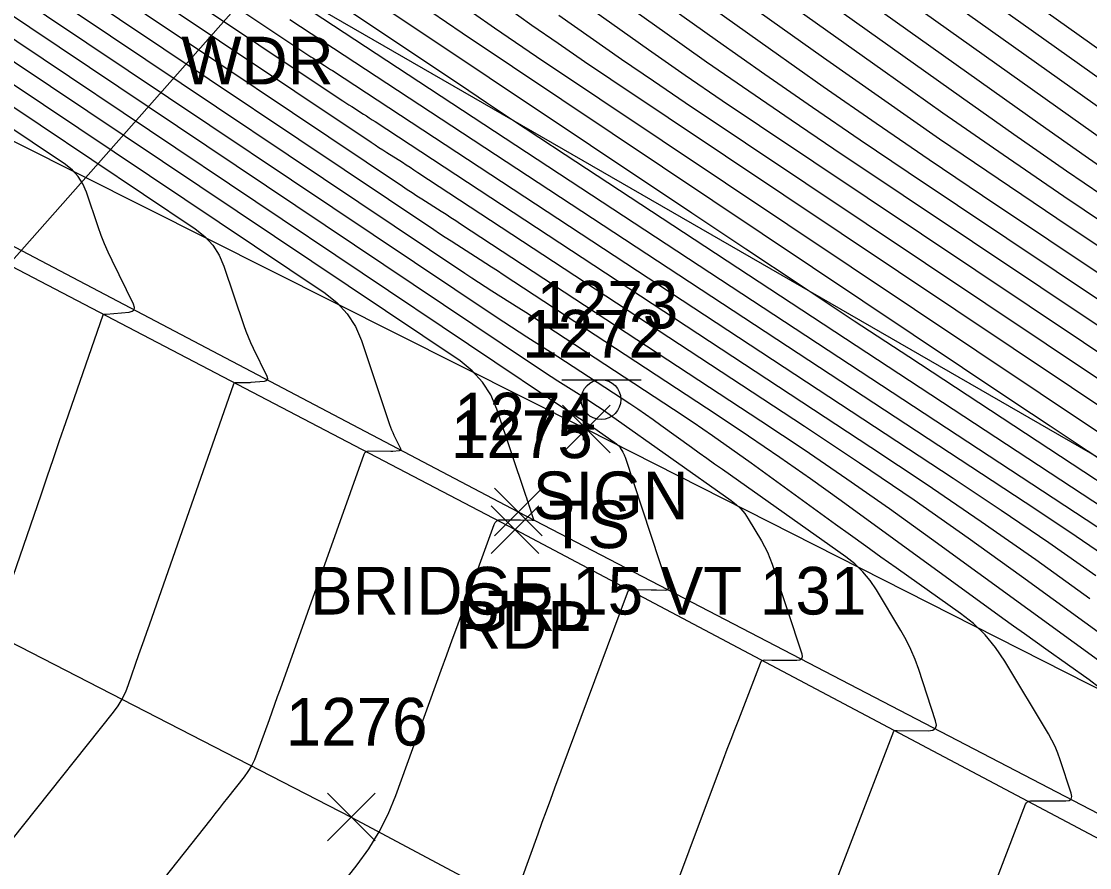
# Model space of a CAD drawing. Extents: x 1650836 to 1652450, y 332578 to 333908.
# Drawn here: x 1652137.1 to 1652181.92, y 332766.98 to 332802.49 of the extents above; entities that cross this region are included whole.
import ezdxf

# ---------------------------------------------------------------- set-up
doc = ezdxf.new("R2010")
doc.units = 0
for name, color, linetype in [('DCP', 7, 'Continuous'), ('L_A', 7, 'Continuous'), ('L_I', 7, 'Continuous'), ('L_TIC', 7, 'Continuous'), ('LAWA', 7, 'Continuous'), ('LELB', 7, 'Continuous'), ('LSOGCMA', 7, 'Continuous'), ('LSOGCMI', 7, 'Continuous'), ('P_A', 7, 'Continuous'), ('P_I', 7, 'Continuous'), ('P_TIC', 7, 'Continuous'), ('PET', 7, 'Continuous'), ('PRC', 7, 'Continuous'), ('R_A', 7, 'Continuous'), ('R_I', 7, 'Continuous'), ('R_TIC', 7, 'Continuous'), ('RGR', 7, 'Continuous'), ('S_A', 7, 'Continuous'), ('S_C', 7, 'Continuous'), ('S_I', 7, 'Continuous'), ('SSGN', 7, 'Continuous')]:
    doc.layers.add(name, color=color, linetype=linetype)

msp = doc.modelspace()

# ---------------------------------------------------------------- linework, layer by layer
at = {"layer": 'DCP'}
msp.add_lwpolyline([(1652097.436, 332748.039), (1652173.064, 332833.561)], dxfattribs=at)
at = {"layer": 'L_TIC'}
for points in [[(1652159.81, 332784.384), (1652161.81, 332786.384)], [(1652161.81, 332784.384), (1652159.81, 332786.384)]]:
    msp.add_lwpolyline(points, dxfattribs=at)
at = {"layer": 'LAWA'}
msp.add_lwpolyline([(1652408.76, 332665.713), (1652363.38, 332695.402), (1652324.46, 332714.991), (1652289.155, 332735.895), (1652253.497, 332747.946), (1652218.614, 332766.122), (1652198.198, 332775.017), (1652146.456, 332804.843), (1652136.841, 332807.592), (1652091.374, 332831.511), (1652057.601, 332848.138), (1652027.653, 332867.625)], dxfattribs=at)
at = {"layer": 'LELB'}
msp.add_lwpolyline([(1652023.441, 332859.649), (1652034.235, 332853.429), (1652052.246, 332842.357), (1652084.686, 332826.36), (1652123.711, 332804.04), (1652160.81, 332785.384), (1652195.281, 332767.897), (1652235.573, 332746.682), (1652255.289, 332735.81), (1652296.57, 332712.591), (1652348.8, 332686.345), (1652380.841, 332668.301), (1652404.073, 332656.539)], dxfattribs=at)
at = {"layer": 'LSOGCMA'}
for points in [[(1652192.271, 332793.06), (1652191.611, 332793.511), (1652190.679, 332794.159), (1652189.751, 332794.813), (1652162.63, 332814.09)], [(1652210.348, 332769.549), (1652210.332, 332769.56), (1652209.691, 332770.012), (1652209.05, 332770.464), (1652208.411, 332770.918), (1652202.726, 332774.956), (1652202.301, 332775.254), (1652201.873, 332775.548), (1652201.442, 332775.838), (1652201.008, 332776.124), (1652199.268, 332777.257), (1652198.833, 332777.541), (1652198.399, 332777.826), (1652197.966, 332778.113), (1652197.534, 332778.401), (1652168.073, 332798.103), (1652166.511, 332799.156), (1652164.957, 332800.22), (1652163.41, 332801.294), (1652161.871, 332802.38), (1652153.245, 332808.511)], [(1652129.2, 332803.974), (1652144.4, 332793.781), (1652144.8, 332793.465), (1652145.134, 332793.098), (1652145.4, 332792.68), (1652145.6, 332792.211), (1652146.436, 332789.728), (1652146.521, 332789.487), (1652146.615, 332789.249), (1652146.716, 332789.014), (1652146.824, 332788.783), (1652147.405, 332787.595), (1652147.433, 332787.509), (1652147.423, 332787.445), (1652147.374, 332787.403), (1652147.286, 332787.382), (1652146.735, 332787.329), (1652146.691, 332787.325), (1652146.646, 332787.323), (1652146.601, 332787.321), (1652146.556, 332787.321), (1652146.093, 332787.326), (1652146.064, 332787.322), (1652146.04, 332787.311), (1652146.021, 332787.292), (1652146.008, 332787.266), (1652142.46, 332777.156), (1652142.35, 332776.844), (1652142.241, 332776.531), (1652142.132, 332776.218), (1652142.023, 332775.905), (1652141.587, 332774.652), (1652141.466, 332774.346), (1652141.321, 332774.053), (1652141.151, 332773.773), (1652140.957, 332773.507), (1652137.194, 332768.775), (1652136.758, 332768.228)], [(1652143.66, 332803.799), (1652150.474, 332799.23), (1652150.595, 332799.149), (1652150.717, 332799.068), (1652150.84, 332798.989), (1652150.963, 332798.91), (1652151.456, 332798.597), (1652151.579, 332798.518), (1652151.702, 332798.439), (1652151.824, 332798.36), (1652151.947, 332798.28), (1652172.746, 332784.625), (1652175.072, 332783.078), (1652177.379, 332781.504), (1652179.667, 332779.903), (1652181.936, 332778.274)]]:
    msp.add_lwpolyline(points, dxfattribs=at)
at = {"layer": 'LSOGCMI'}
for points in [[(1652163.362, 332814.795), (1652192.807, 332793.866)], [(1652191.755, 332792.283), (1652191.471, 332792.472), (1652190.206, 332793.324), (1652188.948, 332794.186), (1652187.696, 332795.056), (1652186.45, 332795.935), (1652161.897, 332813.386)], [(1652161.078, 332812.743), (1652183.149, 332797.056), (1652184.713, 332795.952), (1652186.285, 332794.86), (1652187.865, 332793.779), (1652189.452, 332792.709), (1652191.243, 332791.512)], [(1652160.099, 332812.214), (1652179.848, 332798.177), (1652181.73, 332796.849), (1652183.622, 332795.535), (1652185.524, 332794.234), (1652187.434, 332792.946), (1652190.731, 332790.741)], [(1652211.579, 332775.823), (1652210.221, 332776.757), (1652208.854, 332777.677), (1652207.477, 332778.583), (1652201.697, 332782.345), (1652200.275, 332783.274), (1652198.856, 332784.207), (1652197.439, 332785.145), (1652196.026, 332786.087), (1652185.416, 332793.183), (1652183.182, 332794.688), (1652180.959, 332796.209), (1652178.748, 332797.746), (1652176.547, 332799.299), (1652159.12, 332811.685)], [(1652217.504, 332770.432), (1652211.296, 332774.841), (1652210.067, 332775.704), (1652208.829, 332776.555), (1652207.583, 332777.393), (1652206.329, 332778.219), (1652201.292, 332781.497), (1652200.035, 332782.318), (1652198.779, 332783.144), (1652197.527, 332783.973), (1652196.277, 332784.806), (1652183.397, 332793.42), (1652180.841, 332795.143), (1652178.297, 332796.884), (1652175.765, 332798.643), (1652173.246, 332800.42), (1652158.141, 332811.156)], [(1652217.634, 332769.145), (1652209.582, 332774.864), (1652208.514, 332775.614), (1652207.438, 332776.354), (1652206.355, 332777.082), (1652205.265, 332777.8), (1652200.887, 332780.649), (1652199.794, 332781.363), (1652198.703, 332782.08), (1652197.615, 332782.801), (1652196.528, 332783.525), (1652180.544, 332794.215), (1652178.081, 332795.875), (1652175.63, 332797.552), (1652173.19, 332799.247), (1652170.763, 332800.959), (1652157.161, 332810.627)], [(1652156.182, 332810.098), (1652168.54, 332801.315), (1652170.745, 332799.759), (1652172.961, 332798.219), (1652175.188, 332796.695), (1652177.426, 332795.187), (1652196.78, 332782.244), (1652197.703, 332781.629), (1652198.627, 332781.017), (1652199.554, 332780.407), (1652200.482, 332779.801), (1652204.2, 332777.381), (1652205.127, 332776.771), (1652206.047, 332776.152), (1652206.961, 332775.524), (1652207.868, 332774.887), (1652212.045, 332771.92)], [(1652155.203, 332809.569), (1652166.317, 332801.67), (1652168.3, 332800.271), (1652170.293, 332798.886), (1652172.296, 332797.515), (1652174.309, 332796.159), (1652197.031, 332780.963), (1652197.79, 332780.457), (1652198.551, 332779.953), (1652199.314, 332779.452), (1652200.078, 332778.953), (1652203.136, 332776.962), (1652203.899, 332776.46), (1652204.656, 332775.951), (1652205.407, 332775.434), (1652206.154, 332774.91), (1652211.479, 332771.128)], [(1652210.912, 332770.336), (1652204.44, 332774.933), (1652203.854, 332775.344), (1652203.264, 332775.75), (1652202.67, 332776.149), (1652202.072, 332776.543), (1652199.673, 332778.105), (1652199.073, 332778.496), (1652198.475, 332778.889), (1652197.878, 332779.285), (1652197.282, 332779.682), (1652171.191, 332797.131), (1652169.404, 332798.336), (1652167.625, 332799.553), (1652165.855, 332800.783), (1652164.094, 332802.025), (1652154.224, 332809.04)], [(1652146.574, 332804.702), (1652183.123, 332780.708), (1652184.5, 332779.792), (1652185.867, 332778.859), (1652187.222, 332777.911), (1652188.566, 332776.946), (1652195.288, 332772.06), (1652195.944, 332771.586), (1652196.601, 332771.114), (1652197.261, 332770.646), (1652197.922, 332770.18), (1652200.572, 332768.322), (1652201.234, 332767.856), (1652201.893, 332767.388), (1652202.55, 332766.916), (1652203.206, 332766.441), (1652215.938, 332757.178)], [(1652136.468, 332778.35), (1652137.929, 332782.624), (1652138.188, 332783.382), (1652138.448, 332784.14), (1652138.708, 332784.897), (1652138.969, 332785.655), (1652140.528, 332790.174), (1652140.533, 332790.185), (1652140.541, 332790.192), (1652140.551, 332790.197), (1652140.562, 332790.198), (1652140.614, 332790.198), (1652140.627, 332790.198), (1652140.64, 332790.198), (1652140.653, 332790.199), (1652140.666, 332790.2), (1652141.621, 332790.292), (1652141.755, 332790.324), (1652141.83, 332790.389), (1652141.846, 332790.487), (1652141.804, 332790.618), (1652140.907, 332792.451), (1652140.744, 332792.799), (1652140.592, 332793.151), (1652140.452, 332793.508), (1652140.324, 332793.87), (1652139.833, 332795.327), (1652139.686, 332795.673), (1652139.49, 332795.981), (1652139.244, 332796.251), (1652138.949, 332796.484), (1652127.754, 332803.991)], [(1652130.646, 332803.956), (1652149.851, 332791.078), (1652150.356, 332790.679), (1652150.778, 332790.215), (1652151.115, 332789.687), (1652151.367, 332789.094), (1652152.553, 332785.572), (1652152.593, 332785.459), (1652152.636, 332785.347), (1652152.684, 332785.237), (1652152.735, 332785.129), (1652153.007, 332784.572), (1652153.02, 332784.532), (1652153.015, 332784.502), (1652152.992, 332784.482), (1652152.951, 332784.472), (1652152.693, 332784.447), (1652152.672, 332784.446), (1652152.651, 332784.444), (1652152.63, 332784.444), (1652152.609, 332784.444), (1652151.67, 332784.453), (1652151.602, 332784.445), (1652151.546, 332784.419), (1652151.503, 332784.376), (1652151.472, 332784.315), (1652147.957, 332774.47), (1652147.841, 332774.146), (1652147.725, 332773.823), (1652147.609, 332773.499), (1652147.493, 332773.176), (1652146.986, 332771.768), (1652146.881, 332771.508), (1652146.756, 332771.258), (1652146.611, 332771.02), (1652146.446, 332770.793), (1652145.747, 332769.906), (1652145.572, 332769.684), (1652145.397, 332769.462), (1652145.222, 332769.241), (1652145.047, 332769.019), (1652138.333, 332760.539)], [(1652149.105, 332764.442), (1652151.191, 332767.091), (1652151.684, 332767.769), (1652152.117, 332768.48), (1652152.493, 332769.224), (1652152.809, 332770), (1652154.723, 332775.272), (1652154.952, 332775.903), (1652155.181, 332776.534), (1652155.41, 332777.165), (1652155.639, 332777.796), (1652156.939, 332781.376), (1652156.986, 332781.466), (1652157.05, 332781.53), (1652157.133, 332781.568), (1652157.233, 332781.58), (1652157.739, 332781.575), (1652157.815, 332781.574), (1652157.891, 332781.573), (1652157.968, 332781.572), (1652158.044, 332781.57), (1652158.537, 332781.559), (1652158.561, 332781.558), (1652158.599, 332781.558), (1652158.606, 332781.559), (1652158.61, 332781.562), (1652158.612, 332781.567), (1652158.611, 332781.574), (1652158.412, 332782.178), (1652158.377, 332782.281), (1652158.343, 332782.384), (1652158.309, 332782.487), (1652158.274, 332782.59), (1652157.055, 332786.212), (1652156.797, 332786.817), (1652156.453, 332787.356), (1652156.023, 332787.83), (1652155.507, 332788.238), (1652132.092, 332803.939)], [(1652133.538, 332803.921), (1652160.33, 332785.956), (1652160.387, 332785.918), (1652160.444, 332785.88), (1652160.502, 332785.843), (1652160.56, 332785.806), (1652160.792, 332785.658), (1652160.85, 332785.621), (1652160.907, 332785.583), (1652160.964, 332785.545), (1652161.02, 332785.505), (1652162.076, 332784.759), (1652162.12, 332784.725), (1652162.159, 332784.687), (1652162.195, 332784.645), (1652162.226, 332784.599), (1652162.341, 332784.406), (1652162.368, 332784.357), (1652162.393, 332784.307), (1652162.415, 332784.256), (1652162.434, 332784.203), (1652164.227, 332778.764), (1652164.239, 332778.698), (1652164.225, 332778.651), (1652164.184, 332778.623), (1652164.118, 332778.614), (1652163.755, 332778.616), (1652163.697, 332778.616), (1652163.64, 332778.617), (1652163.582, 332778.618), (1652163.525, 332778.619), (1652162.727, 332778.637), (1652162.657, 332778.63), (1652162.6, 332778.604), (1652162.555, 332778.561), (1652162.523, 332778.499), (1652159.476, 332770.316), (1652159.297, 332769.835), (1652159.119, 332769.353), (1652158.943, 332768.87), (1652158.767, 332768.388), (1652158.066, 332766.457)], [(1652134.984, 332803.904), (1652158.506, 332788.131), (1652158.781, 332787.948), (1652159.057, 332787.767), (1652159.333, 332787.587), (1652159.611, 332787.41), (1652160.725, 332786.702), (1652161.002, 332786.523), (1652161.277, 332786.341), (1652161.55, 332786.156), (1652161.82, 332785.967), (1652166.888, 332782.388), (1652167.098, 332782.223), (1652167.287, 332782.039), (1652167.456, 332781.837), (1652167.604, 332781.615), (1652168.157, 332780.692), (1652168.289, 332780.458), (1652168.407, 332780.218), (1652168.511, 332779.971), (1652168.602, 332779.719), (1652169.844, 332775.954), (1652169.866, 332775.829), (1652169.839, 332775.74), (1652169.763, 332775.686), (1652169.636, 332775.669), (1652168.876, 332775.673), (1652168.804, 332775.674), (1652168.731, 332775.675), (1652168.658, 332775.676), (1652168.585, 332775.677), (1652168.294, 332775.684), (1652168.227, 332775.677), (1652168.172, 332775.652), (1652168.128, 332775.611), (1652168.096, 332775.551), (1652167.186, 332773.185), (1652167.026, 332772.768), (1652166.866, 332772.35), (1652166.708, 332771.932), (1652166.551, 332771.514), (1652163.667, 332763.821)], [(1652144.718, 332804.041), (1652149.163, 332801.06), (1652149.245, 332801.006), (1652149.327, 332800.952), (1652149.41, 332800.898), (1652149.493, 332800.845), (1652149.825, 332800.634), (1652149.908, 332800.581), (1652149.991, 332800.528), (1652150.073, 332800.474), (1652150.156, 332800.421), (1652176.205, 332783.319), (1652178.215, 332781.983), (1652180.208, 332780.623), (1652182.185, 332779.239)], [(1652149.367, 332803.935), (1652155.521, 332799.82), (1652156.618, 332799.088), (1652157.716, 332798.359), (1652158.816, 332797.632), (1652159.917, 332796.907), (1652186.581, 332779.402), (1652187.643, 332778.696), (1652188.696, 332777.978), (1652189.74, 332777.247), (1652190.776, 332776.503), (1652195.29, 332773.222), (1652196.128, 332772.615), (1652196.969, 332772.012), (1652197.813, 332771.413), (1652198.659, 332770.817), (1652202.049, 332768.441), (1652202.895, 332767.845), (1652203.739, 332767.245), (1652204.58, 332766.642), (1652205.418, 332766.035), (1652221.704, 332754.186)], [(1652168.883, 332760.159), (1652173.712, 332772.711), (1652173.718, 332772.721), (1652173.726, 332772.728), (1652173.735, 332772.732), (1652173.747, 332772.734), (1652173.797, 332772.732), (1652173.822, 332772.732), (1652173.847, 332772.732), (1652175.155, 332772.725), (1652175.341, 332772.75), (1652175.454, 332772.828), (1652175.494, 332772.96), (1652175.46, 332773.144), (1652174.752, 332775.293), (1652174.599, 332775.717), (1652174.424, 332776.13), (1652174.226, 332776.532), (1652174.005, 332776.925), (1652172.983, 332778.632), (1652172.717, 332779.029), (1652172.414, 332779.392), (1652172.075, 332779.721), (1652171.7, 332780.016), (1652166.514, 332783.679), (1652166.19, 332783.909), (1652165.867, 332784.14), (1652165.545, 332784.371), (1652165.223, 332784.604), (1652163.939, 332785.538), (1652163.616, 332785.769), (1652163.291, 332785.997), (1652162.963, 332786.22), (1652162.633, 332786.44), (1652160.901, 332787.577), (1652160.579, 332787.787), (1652160.257, 332787.996), (1652159.934, 332788.204), (1652159.61, 332788.411), (1652158.313, 332789.235), (1652157.99, 332789.442), (1652157.667, 332789.651), (1652157.346, 332789.862), (1652157.026, 332790.075), (1652136.43, 332803.886)], [(1652177.74, 332765.74), (1652179.24, 332769.64), (1652179.273, 332769.702), (1652179.319, 332769.746), (1652179.376, 332769.773), (1652179.445, 332769.782), (1652179.747, 332769.783), (1652179.823, 332769.784), (1652179.898, 332769.784), (1652179.973, 332769.784), (1652180.049, 332769.783), (1652180.92, 332769.779), (1652181.062, 332769.798), (1652181.149, 332769.858), (1652181.179, 332769.959), (1652181.154, 332770.1), (1652180.693, 332771.497), (1652180.591, 332771.78), (1652180.474, 332772.057), (1652180.342, 332772.326), (1652180.194, 332772.589), (1652178.361, 332775.649), (1652177.978, 332776.221), (1652177.542, 332776.745), (1652177.053, 332777.219), (1652176.511, 332777.645), (1652173.805, 332779.556), (1652173.165, 332780.01), (1652172.527, 332780.465), (1652171.891, 332780.923), (1652171.256, 332781.383), (1652167.722, 332783.952), (1652166.918, 332784.529), (1652166.107, 332785.096), (1652165.29, 332785.654), (1652164.466, 332786.201), (1652159.11, 332789.718), (1652158.828, 332789.902), (1652158.546, 332790.085), (1652158.263, 332790.267), (1652157.979, 332790.448), (1652156.843, 332791.17), (1652156.56, 332791.352), (1652156.277, 332791.535), (1652155.996, 332791.72), (1652155.716, 332791.906), (1652137.876, 332803.869)], [(1652182.333, 332774.525), (1652181.901, 332774.865), (1652180.089, 332776.145), (1652179.636, 332776.466), (1652179.185, 332776.788), (1652178.734, 332777.112), (1652178.285, 332777.437), (1652171.504, 332782.366), (1652170.219, 332783.288), (1652168.923, 332784.195), (1652167.617, 332785.087), (1652166.3, 332785.963), (1652157.319, 332791.858), (1652157.077, 332792.016), (1652156.835, 332792.174), (1652156.592, 332792.33), (1652156.348, 332792.485), (1652155.373, 332793.105), (1652155.13, 332793.261), (1652154.887, 332793.418), (1652154.646, 332793.577), (1652154.405, 332793.737), (1652139.322, 332803.851)], [(1652140.768, 332803.834), (1652153.095, 332795.568), (1652153.296, 332795.434), (1652153.497, 332795.302), (1652153.7, 332795.17), (1652153.903, 332795.04), (1652154.718, 332794.523), (1652154.921, 332794.393), (1652155.124, 332794.262), (1652155.326, 332794.131), (1652155.528, 332793.999), (1652168.133, 332785.724), (1652169.944, 332784.52), (1652171.739, 332783.295), (1652173.52, 332782.048), (1652175.287, 332780.78), (1652185.315, 332773.491)], [(1652192.345, 332769.545), (1652179.07, 332779.194), (1652176.822, 332780.808), (1652174.555, 332782.394), (1652172.27, 332783.953), (1652169.966, 332785.485), (1652153.737, 332796.139), (1652153.575, 332796.245), (1652153.413, 332796.351), (1652153.25, 332796.456), (1652153.087, 332796.56), (1652152.433, 332796.975), (1652152.27, 332797.08), (1652152.107, 332797.185), (1652151.946, 332797.291), (1652151.784, 332797.399), (1652142.214, 332803.816)], [(1652209.247, 332768.01), (1652208.596, 332768.468), (1652201.465, 332773.467), (1652201.227, 332773.634), (1652200.989, 332773.802), (1652200.751, 332773.969), (1652200.514, 332774.138), (1652199.297, 332775.002), (1652199.194, 332775.074), (1652199.09, 332775.146), (1652198.986, 332775.216), (1652198.88, 332775.285), (1652198.458, 332775.561), (1652198.352, 332775.629), (1652198.247, 332775.699), (1652198.142, 332775.768), (1652198.037, 332775.838), (1652161.838, 332800.047), (1652160.726, 332800.796), (1652159.62, 332801.553), (1652158.52, 332802.318), (1652157.424, 332803.091)], [(1652148.365, 332802.561), (1652179.664, 332782.014), (1652181.357, 332780.887), (1652183.037, 332779.741)], [(1652227.471, 332751.194), (1652207.63, 332765.629), (1652206.609, 332766.368), (1652205.584, 332767.103), (1652204.557, 332767.834), (1652203.526, 332768.56), (1652198.798, 332771.874), (1652198.066, 332772.389), (1652197.336, 332772.908), (1652196.608, 332773.43), (1652195.883, 332773.955), (1652192.986, 332776.061), (1652192.258, 332776.583), (1652191.525, 332777.096), (1652190.786, 332777.601), (1652190.04, 332778.096), (1652174.332, 332788.409), (1652172.051, 332789.91), (1652169.773, 332791.415), (1652167.499, 332792.926), (1652165.228, 332794.441), (1652152.485, 332802.963)], [(1652234.419, 332747.342), (1652209.842, 332765.223), (1652208.638, 332766.095), (1652207.43, 332766.961), (1652206.219, 332767.823), (1652205.003, 332768.679), (1652198.544, 332773.206), (1652198.122, 332773.503), (1652197.701, 332773.802), (1652197.282, 332774.103), (1652196.864, 332774.405), (1652195.196, 332775.618), (1652194.777, 332775.919), (1652194.354, 332776.214), (1652193.928, 332776.505), (1652193.499, 332776.791), (1652184.956, 332782.399), (1652183.39, 332783.429), (1652181.826, 332784.463), (1652180.264, 332785.501), (1652178.704, 332786.542), (1652155.602, 332801.991), (1652154.942, 332802.437), (1652154.284, 332802.887)], [(1652156.074, 332802.83), (1652156.952, 332802.22), (1652157.834, 332801.617), (1652158.72, 332801.019), (1652193.053, 332778.058), (1652193.464, 332777.784), (1652193.877, 332777.51), (1652194.29, 332777.237), (1652194.703, 332776.965), (1652196.958, 332775.485), (1652197.071, 332775.409), (1652197.183, 332775.333), (1652197.295, 332775.255), (1652197.405, 332775.175), (1652197.846, 332774.855), (1652197.956, 332774.775), (1652198.067, 332774.696), (1652198.178, 332774.617), (1652198.289, 332774.539), (1652206.48, 332768.797), (1652207.88, 332767.811), (1652208.692, 332767.234)], [(1652209.798, 332768.78), (1652206.558, 332771.051), (1652205.948, 332771.479), (1652205.34, 332771.907), (1652204.732, 332772.337), (1652204.125, 332772.767), (1652201.011, 332774.979), (1652200.747, 332775.164), (1652200.482, 332775.347), (1652200.214, 332775.527), (1652199.944, 332775.704), (1652198.863, 332776.409), (1652198.592, 332776.585), (1652198.323, 332776.762), (1652198.054, 332776.94), (1652197.785, 332777.119), (1652164.956, 332799.075), (1652163.619, 332799.976), (1652162.288, 332800.886), (1652160.965, 332801.806), (1652159.648, 332802.735)]]:
    msp.add_lwpolyline(points, dxfattribs=at)
at = {"layer": 'P_TIC'}
for points in [[(1652156.819, 332780.161), (1652158.819, 332782.161)], [(1652158.819, 332780.161), (1652156.819, 332782.161)], [(1652149.944, 332768.103), (1652151.944, 332770.103)], [(1652151.944, 332768.103), (1652149.944, 332770.103)]]:
    msp.add_lwpolyline(points, dxfattribs=at)
at = {"layer": 'PET'}
msp.add_lwpolyline([(1651782.185, 332994.087), (1651800.504, 332980.945), (1651823.969, 332965.234), (1651861.092, 332941.311), (1651895.497, 332920.881), (1651932.1, 332899.878), (1651964.344, 332882.546), (1651997.084, 332865.287), (1652030.302, 332847.665), (1652049.548, 332837.673), (1652081.974, 332820.953), (1652121.026, 332800.401), (1652157.819, 332781.161), (1652191.945, 332763.077), (1652232.596, 332742.33), (1652251.93, 332731.59), (1652295.202, 332708.727), (1652345.726, 332682.336), (1652379.152, 332664.868), (1652402.111, 332652.828)], dxfattribs=at)
at = {"layer": 'PRC'}
msp.add_lwpolyline([(1651773.612, 332982.822), (1651792.672, 332969.525), (1651816.542, 332953.47), (1651853.779, 332929.89), (1651888.829, 332909.027), (1651925.09, 332888.189), (1651957.726, 332870.48), (1651982.519, 332857.297), (1652019.654, 332837.681), (1652042.767, 332825.192), (1652076.048, 332808.311), (1652114.48, 332787.851), (1652150.944, 332769.103), (1652185.791, 332750.516), (1652225.777, 332729.89), (1652246.28, 332718.635), (1652288.707, 332696.529), (1652339.002, 332669.86), (1652372.556, 332652.699), (1652395.364, 332640.33)], dxfattribs=at)
at = {"layer": 'R_TIC'}
for points in [[(1652156.949, 332780.905), (1652158.949, 332782.905)], [(1652158.949, 332780.905), (1652156.949, 332782.905)]]:
    msp.add_lwpolyline(points, dxfattribs=at)
at = {"layer": 'RGR'}
msp.add_lwpolyline([(1652023.441, 332859.649), (1652024.915, 332854.382), (1652030.806, 332848.332), (1652049.928, 332838.521), (1652082.838, 332821.514), (1652121.63, 332801.012), (1652157.949, 332781.905), (1652192.709, 332763.821), (1652232.753, 332742.853), (1652252.846, 332732.22), (1652295.713, 332710.152), (1652346.443, 332683.145), (1652379.801, 332666.008), (1652402.772, 332654.006)], dxfattribs=at)
at = {"layer": 'SSGN'}
for p, q in [((1652159.778, 332787.454), (1652163.111, 332787.454)), ((1652161.424, 332786.62), (1652161.424, 332786.62))]:
    msp.add_line(p, q, dxfattribs=at)
msp.add_circle((1652161.424, 332786.62), 0.833, dxfattribs=at)

# ---------------------------------------------------------------- texts
at = {"layer": 'L_A'}
for s, p in [('WDR', (1652143.818, 332799.843)), ('TS', (1652159.219, 332780.384))]:
    msp.add_text(s, height=2, dxfattribs=at).set_placement(p)
at = {"layer": 'L_I'}
msp.add_text('1272', height=2, dxfattribs=at).set_placement((1652158.117, 332788.384))
at = {"layer": 'P_A'}
msp.add_text('RDP', height=2, dxfattribs=at).set_placement((1652155.307, 332776.161))
at = {"layer": 'P_I'}
for s, p in [('1275', (1652155.127, 332784.161)), ('1276', (1652148.196, 332772.103))]:
    msp.add_text(s, height=2, dxfattribs=at).set_placement(p)
at = {"layer": 'R_A'}
msp.add_text('GRL', height=2, dxfattribs=at).set_placement((1652155.493, 332776.905))
at = {"layer": 'R_I'}
msp.add_text('1274', height=2, dxfattribs=at).set_placement((1652155.257, 332784.905))
at = {"layer": 'S_A'}
msp.add_text('SIGN', height=2, dxfattribs=at).set_placement((1652158.563, 332781.6))
at = {"layer": 'S_C'}
msp.add_text('BRIDGE 15 VT 131', height=2, dxfattribs=at).set_placement((1652149.217, 332777.6))
at = {"layer": 'S_I'}
msp.add_text('1273', height=2, dxfattribs=at).set_placement((1652158.712, 332789.6))

doc.saveas('drawing.dxf')
